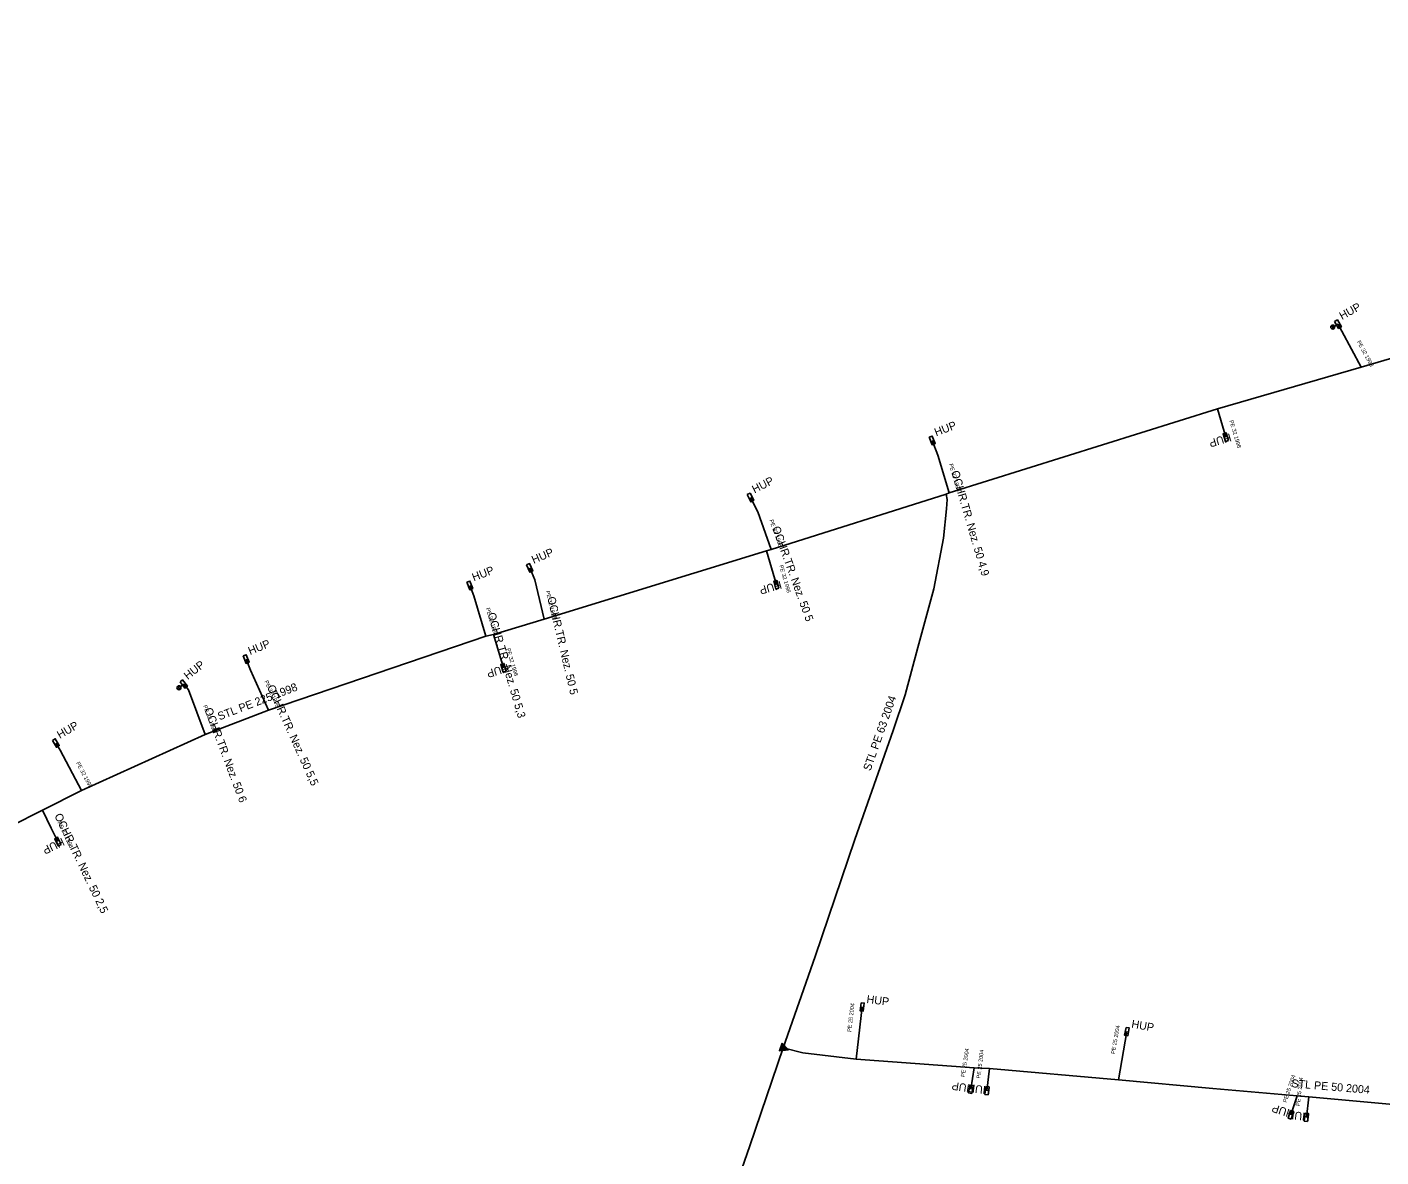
# Model space of a CAD drawing. Extents: x -741240 to -740302, y -1028024 to -1027535.
# Drawn here: x -740998.7 to -740829.5, y -1027905 to -1027763.7 of the extents above; entities that cross this region are included whole.
import ezdxf

# ---------------------------------------------------------------- set-up
doc = ezdxf.new("R2010")
doc.units = 0
for name, color, linetype in [('ST OP Chráni_ka - provoz', 7, 'Continuous'), ('ST Úsek p_ípojky - provoz', 7, 'Continuous'), ('ST Úsek plynovodu - provoz', 7, 'Continuous'), ('ST_HUP_22_23_popis', 7, 'Continuous'), ('Vrstva 1', 7, 'Continuous')]:
    doc.layers.add(name, color=color, linetype=linetype)

msp = doc.modelspace()

# ---------------------------------------------------------------- linework, layer by layer
at = {"layer": 'ST OP Chráni_ka - provoz'}
for points in [[(-740831.91, -1027806.24), (-740834.34, -1027801.75)], [(-740883.44, -1027821.98), (-740884.82, -1027817.27)], [(-740905.65, -1027829.03), (-740907.35, -1027824.34)], [(-740934.04, -1027837.75), (-740935.2, -1027832.86)], [(-740941.34, -1027839.9), (-740942.82, -1027834.84)], [(-740968.49, -1027849.13), (-740970.73, -1027844.15)], [(-740976.4, -1027852.18), (-740978.51, -1027846.6)], [(-740991.88, -1027859.18), (-740994.55, -1027854.13)], [(-740996.72, -1027861.64), (-740995.65, -1027863.87)]]:
    msp.add_lwpolyline(points, dxfattribs=at)
at = {"layer": 'ST Úsek p_ípojky - provoz'}
for points in [[(-740831.91, -1027806.24), (-740834.34, -1027801.75), (-740834.82, -1027800.87)], [(-740849.9, -1027811.48), (-740848.84, -1027815.02)], [(-740883.44, -1027821.98), (-740884.82, -1027817.27), (-740885.54, -1027815.41)], [(-740905.65, -1027829.03), (-740907.35, -1027824.34), (-740908.25, -1027822.55)], [(-740906.26, -1027829.23), (-740905.02, -1027833.45)], [(-740934.04, -1027837.75), (-740935.2, -1027832.86), (-740935.85, -1027831.35)], [(-740941.34, -1027839.9), (-740942.82, -1027834.84), (-740943.33, -1027833.53)], [(-740940.36, -1027839.67), (-740939.12, -1027843.83)], [(-740968.49, -1027849.13), (-740970.73, -1027844.15), (-740971.29, -1027842.75)], [(-740976.4, -1027852.18), (-740978.51, -1027846.6), (-740979.09, -1027845.87)], [(-740991.88, -1027859.18), (-740994.55, -1027854.13), (-740995.07, -1027853.24)], [(-740996.72, -1027861.64), (-740995.65, -1027863.87), (-740994.81, -1027865.57)], [(-740895.06, -1027892.75), (-740894.29, -1027886.24)], [(-740862.24, -1027895.33), (-740861.2, -1027889.32)], [(-740880.28, -1027893.83), (-740880.72, -1027896.53)], [(-740878.36, -1027893.92), (-740878.7, -1027896.71)], [(-740839.91, -1027897.34), (-740840.71, -1027899.74)], [(-740838.48, -1027897.47), (-740838.78, -1027900.04)]]:
    msp.add_lwpolyline(points, dxfattribs=at)
at = {"layer": 'ST Úsek plynovodu - provoz'}
for points in [[(-740883.81, -1027822.11), (-740883.44, -1027821.98), (-740849.9, -1027811.48), (-740831.91, -1027806.24), (-740823.13, -1027803.69), (-740789.36, -1027795.01), (-740788.17, -1027794.71), (-740783.44, -1027784.02), (-740778.93, -1027773.97), (-740777.89, -1027770.09), (-740779.07, -1027764.12), (-740779.14, -1027763.73)], [(-741050.78, -1027895.98), (-741052.25, -1027892.88), (-741053.77, -1027890.07), (-741032.67, -1027879.74), (-741030.5, -1027878.67), (-741015.06, -1027870.82), (-741012.59, -1027869.65), (-740996.72, -1027861.64), (-740991.88, -1027859.18), (-740976.4, -1027852.18), (-740968.49, -1027849.13), (-740941.34, -1027839.9), (-740940.36, -1027839.67), (-740934.04, -1027837.75), (-740906.26, -1027829.23), (-740905.65, -1027829.03), (-740883.81, -1027822.11)], [(-740883.81, -1027822.11), (-740883.66, -1027822.81), (-740883.75, -1027823.97), (-740884.12, -1027827.64), (-740885.35, -1027833.96), (-740887.34, -1027841.29), (-740888.94, -1027847.2), (-740890.4, -1027851.67), (-740895.2, -1027865.32), (-740900.16, -1027879.92), (-740904.17, -1027891.35)], [(-740904.17, -1027891.35), (-740908.34, -1027903.59), (-740912.76, -1027916.33), (-740913.41, -1027919.19), (-740914.04, -1027924.84), (-740915.38, -1027935.88), (-740916.46, -1027947.48), (-740916.24, -1027948.17), (-740907.33, -1027957.11), (-740907.11, -1027957.65), (-740906.9, -1027960.06)], [(-740904.17, -1027891.35), (-740903.99, -1027891.41)], [(-740903.99, -1027891.41), (-740901.7, -1027891.99), (-740895.06, -1027892.75), (-740880.28, -1027893.83), (-740878.36, -1027893.92), (-740862.24, -1027895.33), (-740850.48, -1027896.44), (-740839.91, -1027897.34), (-740838.48, -1027897.47), (-740818.75, -1027899.28), (-740802.46, -1027900.48), (-740800.38, -1027900.65), (-740799.71, -1027900.69), (-740798.33, -1027900.86), (-740785.58, -1027902.19), (-740778.94, -1027902.34), (-740778.56, -1027902.38), (-740777.45, -1027902.39)]]:
    msp.add_lwpolyline(points, dxfattribs=at)
at = {"layer": 'Vrstva 1'}
for p, q in [((-740834.82, -1027800.87), (-740835.26, -1027801.11)), ((-740979.09, -1027845.87), (-740979.49, -1027846.18))]:
    msp.add_line(p, q, dxfattribs=at)
for points in [[(-740835.24, -1027800.53), (-740834.89, -1027800.34), (-740834.4, -1027801.21), (-740834.75, -1027801.4)], [(-740885.91, -1027815.01), (-740885.53, -1027814.87), (-740885.17, -1027815.8), (-740885.55, -1027815.95)], [(-740848.5, -1027815.44), (-740848.89, -1027815.56), (-740849.18, -1027814.6), (-740848.79, -1027814.48)], [(-740908.65, -1027822.19), (-740908.3, -1027822.01), (-740907.84, -1027822.9), (-740908.2, -1027823.09)], [(-740936.23, -1027830.97), (-740935.86, -1027830.81), (-740935.47, -1027831.73), (-740935.84, -1027831.89)], [(-740943.7, -1027833.13), (-740943.32, -1027832.99), (-740942.96, -1027833.92), (-740943.34, -1027834.07)], [(-740904.69, -1027833.88), (-740905.07, -1027833.99), (-740905.35, -1027833.02), (-740904.97, -1027832.91)], [(-740971.66, -1027842.36), (-740971.29, -1027842.21), (-740970.92, -1027843.14), (-740971.29, -1027843.29)], [(-740938.78, -1027844.25), (-740939.17, -1027844.37), (-740939.46, -1027843.41), (-740939.07, -1027843.29)], [(-740979.55, -1027845.6), (-740979.24, -1027845.35), (-740978.62, -1027846.14), (-740978.94, -1027846.39)], [(-740995.49, -1027852.91), (-740995.15, -1027852.71), (-740994.65, -1027853.57), (-740994.99, -1027853.77)], [(-740994.41, -1027865.93), (-740994.77, -1027866.11), (-740995.21, -1027865.21), (-740994.85, -1027865.03)], [(-740894.43, -1027885.72), (-740894.03, -1027885.76), (-740894.16, -1027886.76), (-740894.55, -1027886.71)], [(-740861.31, -1027888.79), (-740860.92, -1027888.86), (-740861.09, -1027889.84), (-740861.49, -1027889.77)], [(-740904.29, -1027890.77), (-740904.63, -1027891.71), (-740903.52, -1027891.58)], [(-740904.48, -1027891.59), (-740903.73, -1027891.51), (-740904.25, -1027890.96)], [(-740903.94, -1027891.43), (-740904.21, -1027891.15), (-740904.33, -1027891.48)], [(-740880.6, -1027897.05), (-740880.99, -1027896.99), (-740880.84, -1027896), (-740880.44, -1027896.07)], [(-740878.56, -1027897.23), (-740878.95, -1027897.18), (-740878.83, -1027896.19), (-740878.44, -1027896.24)], [(-740840.67, -1027900.28), (-740841.05, -1027900.15), (-740840.74, -1027899.2), (-740840.36, -1027899.33)], [(-740838.64, -1027900.56), (-740839.04, -1027900.51), (-740838.92, -1027899.52), (-740838.52, -1027899.57)]]:
    msp.add_lwpolyline(points, close=True, dxfattribs=at)
for centre, radius in [((-740835.48, -1027801.24), 0.249), ((-740835.52, -1027801.14), 0.0614), ((-740835.42, -1027801.32), 0.0614), ((-740979.68, -1027846.34), 0.249), ((-740979.73, -1027846.25), 0.0614), ((-740979.61, -1027846.41), 0.0614)]:
    msp.add_circle(centre, radius, dxfattribs=at)

# ---------------------------------------------------------------- texts
at = {"layer": 'ST OP Chráni_ka - provoz'}
for s, rotation, p in [('OCHR.TR. Nez. 50 4,9', 286.3302, (-740883.17, -1027819.34)), ('OCHR.TR. Nez. 50 5', 289.9242, (-740905.56, -1027826.34)), ('OCHR.TR. Nez. 50 5', 283.345, (-740933.65, -1027835.07)), ('OCHR.TR. Nez. 50 5,3', 286.3037, (-740941.12, -1027837.09)), ('OCHR.TR. Nez. 50 5,5', 294.2182, (-740968.7, -1027846.23)), ('OCHR.TR. Nez. 50 6', 290.7134, (-740976.52, -1027849.04)), ('OCHR.TR. Nez. 50 2,5', 295.6327, (-740995.28, -1027862.32))]:
    msp.add_text(s, height=1, rotation=rotation, dxfattribs=at).set_placement(p)
at = {"layer": 'ST Úsek p_ípojky - provoz'}
for s, rotation, p in [('PE 32 1998', 298.4224, (-740832.48, -1027803.08)), ('PE 32 1998', 286.6695, (-740848.41, -1027812.96)), ('PE 32 1998', 286.3302, (-740883.45, -1027818.39)), ('PE 32 1998', 289.9242, (-740905.9, -1027825.4)), ('PE 32 1998', 286.3748, (-740904.68, -1027831.06)), ('PE 32 1998', 283.345, (-740933.84, -1027834.27)), ('PE 32 1998', 286.3037, (-740941.32, -1027836.41)), ('PE 32 1998', 286.6019, (-740938.78, -1027841.46)), ('PE 32 1998', 294.2182, (-740969.01, -1027845.54)), ('PE 32 1998', 290.7134, (-740976.68, -1027848.6)), ('PE 32 1998', 297.866, (-740992.57, -1027855.73)), ('PE 32 1998', 295.6327, (-740994.87, -1027863.18)), ('PE 25 2004', 83.2963, (-740895.67, -1027889.38)), ('PE 25 2004', 80.2029, (-740862.71, -1027892.15)), ('PE 25 2004', 80.8303, (-740881.49, -1027895.02)), ('PE 25 2004', 83.184, (-740879.52, -1027895.2)), ('PE 25 2004', 71.6797, (-740841.26, -1027898.23)), ('PE 25 2004', 83.2928, (-740839.62, -1027898.64))]:
    msp.add_text(s, height=0.5, rotation=rotation, dxfattribs=at).set_placement(p)
at = {"layer": 'ST Úsek plynovodu - provoz'}
for s, rotation, p in [('STL PE 225 1998', 21.086, (-740974.62, -1027850.42)), ('STL PE 63 2004', 70.65, (-740893.26, -1027856.8)), ('STL PE 50 2004', 355.1461, (-740840.67, -1027896.27))]:
    msp.add_text(s, height=1, rotation=rotation, dxfattribs=at).set_placement(p)
at = {"layer": 'ST_HUP_22_23_popis'}
for rotation, p in [(29, (-740834.32, -1027800.37)), (21, (-740885.04, -1027814.91)), (197, (-740848.34, -1027814.52)), (27, (-740907.75, -1027822.05)), (23, (-740935.35, -1027830.85)), (21, (-740942.83, -1027833.03)), (196, (-740904.52, -1027832.95)), (22, (-740970.79, -1027842.25)), (38, (-740978.59, -1027845.37)), (197, (-740938.62, -1027843.33)), (30, (-740994.57, -1027852.74)), (206, (-740994.31, -1027865.07)), (353, (-740893.79, -1027885.74)), (350, (-740860.7, -1027888.82)), (171, (-740880.22, -1027896.03)), (173.18, (-740878.2, -1027896.21)), (162, (-740840.21, -1027899.24)), (173, (-740838.28, -1027899.54))]:
    msp.add_text('HUP', height=1, rotation=rotation, dxfattribs=at).set_placement(p)

doc.saveas('drawing.dxf')
